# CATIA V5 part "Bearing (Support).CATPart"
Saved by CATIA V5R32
Part number: Bearing (Support)
Bounding box of the stored display mesh (mm): x -270 to 10, y -39.842 to 39.842, z -34.808 to 139.842
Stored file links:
  D:\PROJECTS\Project 2022\CATIA V5 6R 2022\Resources\Part Files\c16_catia_v5_6r2022_prt\CV Joint-(Fig16-51)\Bearing (Support).CATPart
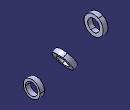
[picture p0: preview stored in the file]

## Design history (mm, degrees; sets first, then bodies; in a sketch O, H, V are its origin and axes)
Body1 (main body)
  Sketch1 on yz-plane, origin (0, 0, 0), H (0, 1, 0), V (0, 0, 1)
    circle A1 centre (0, 0) radius 25
    circle A2 centre (0, 0) radius 35
    radius A1 = 25
    radius A2 = 35
  Pad1: profile Sketch1, direction (1, 0, 0), length 10, mirrored extent
  Sketch2 on zx-plane, origin (0, 0, 0), H (-1, 0, 0), V (0, 0, 1)
    construction line L1 (0, 0) -> (60, 0)
    construction line L2 (60, 0) -> (194.1972, 77.4788)
    line L3 (107.5, 56.2917) -> (124.8205, 66.2917)
    line L4 (124.8205, 66.2917) -> (117.3205, 79.282)
    line L5 (117.3205, 79.282) -> (100, 69.282)
    point P6 (100, 69.282)
    line L6 (100, 69.282) -> (107.5, 56.2917)
    angle L2 L1 = 30
    distance L6 L4 = 20
    length L6 = 15
    distance L3 L2 = 25
    distance P6 V = 100
    length L1 = 60
    horizontal: L1 H
    perpendicularity: L4 L3
    parallelism: L5 L2, L6 L4
  Sketch3 on zx-plane, origin (0, 0, 0), H (-1, 0, 0), V (0, 0, 1)
    line L1 (60, 0) -> (221.9169, 93.4828)
    point P1 (60, 0)
    reference projected line E1 (107.5, 56.2917) -> (124.8205, 66.2917) from Sketch2.L3
    reference projected line E2 (107.5, 56.2917) -> (124.8205, 66.2917) from Sketch2.L3
    distance E2 L1 = 25
    coincidence: P1 H
    parallelism: L1 E1
  Shaft1: profile Sketch2, axis Sketch3.L1, angle 360
  Sketch4 on zx-plane, origin (0, 0, 0), H (-1, 0, 0), V (0, 0, 1)
    construction line L1 (188.3301, 100) -> (395.6544, 100)
    point P3 (260, 132.5)
    line L2 (270, 140) -> (270, 125)
    line L3 (270, 125) -> (250, 125)
    line L4 (250, 125) -> (250, 140)
    line L5 (250, 140) -> (270, 140)
    distance L1 H = 100
    length L5 = 20
    length L4 = 15
    distance L1 L3 = 25
    distance L4 V = 250
    horizontal: L1 H, L3 H, L5 H
    vertical: L2 V, L4 V
    equidistance: L2 L4 P3, L3 L5 P3
  Sketch5 on zx-plane, origin (0, 0, 0), H (-1, 0, 0), V (0, 0, 1)
    line L1 (210.3804, 100) -> (348.9415, 100)
    reference projected line E1 (250, 125) -> (270, 125) from Sketch4.L3
    distance L1 E1 = 25
    horizontal: L1 H
  Shaft2: profile Sketch4, axis Sketch5.L1, angle 360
